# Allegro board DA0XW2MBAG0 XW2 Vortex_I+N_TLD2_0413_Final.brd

Outline 370.48 x 162 mm; copper layers: TOP, GND, IN1, VCC, IN2, IN3, GND1, IN4, GND2, BOTTOM. Coordinates in mm from the lower left corner of the outline.

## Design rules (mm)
net group DFP-S7W4.5(3: nets VGA_XTALIN VGA_XTALOUT
net group W4.5(3)-T1B: nets CLKIN_XTAL_LCP CLKIN_XTAL_LCP_R
net group W4.5(3: nets EC_RST# LPC_ESPI_RESET#_R_R
net group DFP-S3.75(4: nets C_PEG_TXN0 C_PEG_TXN1 C_PEG_TXN2 C_PEG_TXN3 C_PEG_TXN4 C_PEG_TXN5 C_PEG_TXN6 C_PEG_TXN7 C_PEG_TXN8 C_PEG_TXN9 C_PEG_TXN10 C_PEG_TXN11 C_PEG_TXN12 C_PEG_TXN13 C_PEG_TXN14 C_PEG_TXN15 C_PEG_TXP0 C_PEG_TXP1 C_PEG_TXP2 C_PEG_TXP3 C_PEG_TXP4 C_PEG_TXP5 C_PEG_TXP6 C_PEG_TXP7 C_PEG_TXP8 C_PEG_TXP9 C_PEG_TXP10 C_PEG_TXP11 C_PEG_TXP12 C_PEG_TXP13 C_PEG_TXP14 C_PEG_TXP15 PEG_RXN0 PEG_RXN0_C PEG_RXN1 PEG_RXN1_C PEG_RXN2 PEG_RXN2_C PEG_RXN3 PEG_RXN3_C PEG_RXN4 PEG_RXN4_C PEG_RXN5 PEG_RXN5_C PEG_RXN6 PEG_RXN6_C PEG_RXN7 PEG_RXN7_C PEG_RXN8 PEG_RXN8_C PEG_RXN9 PEG_RXN9_C PEG_RXN10 PEG_RXN10_C PEG_RXN11 PEG_RXN11_C PEG_RXN12 PEG_RXN12_C PEG_RXN13 PEG_RXN13_C PEG_RXN14 PEG_RXN14_C PEG_RXN15 PEG_RXN15_C PEG_RXP0 PEG_RXP0_C PEG_RXP1 PEG_RXP1_C PEG_RXP2 PEG_RXP2_C PEG_RXP3 PEG_RXP3_C PEG_RXP4 PEG_RXP4_C PEG_RXP5 PEG_RXP5_C PEG_RXP6 PEG_RXP6_C PEG_RXP7 PEG_RXP7_C PEG_RXP8 PEG_RXP8_C PEG_RXP9 PEG_RXP9_C PEG_RXP10 PEG_RXP10_C PEG_RXP11 PEG_RXP11_C PEG_RXP12 PEG_RXP12_C PEG_RXP13 PEG_RXP13_C PEG_RXP14 PEG_RXP14_C PEG_RXP15 PEG_RXP15_C PEG_TXN0 PEG_TXN1 PEG_TXN2 PEG_TXN3 PEG_TXN4 PEG_TXN5 PEG_TXN6 PEG_TXN7 PEG_TXN8 PEG_TXN9 PEG_TXN10 PEG_TXN11 PEG_TXN12 PEG_TXN13 PEG_TXN14 PEG_TXN15 PEG_TXP0 PEG_TXP1 PEG_TXP2 PEG_TXP3 PEG_TXP4 PEG_TXP5 PEG_TXP6 PEG_TXP7 PEG_TXP8 PEG_TXP9 PEG_TXP10 PEG_TXP11 PEG_TXP12 PEG_TXP13 PEG_TXP14 PEG_TXP15
net group DFP-S4(3.5)W4(3)-T1B: nets DMI_RXN0 DMI_RXN1 DMI_RXN2 DMI_RXN3 DMI_RXP0 DMI_RXP1 DMI_RXP2 DMI_RXP3 DMI_TXN0 DMI_TXN1 DMI_TXN2 DMI_TXN3 DMI_TXP0 DMI_TXP1 DMI_TXP2 DMI_TXP3
net group DFP-S4(3.5)W4(3)-T14B: nets TBTA_DPSRC_AUX_N TBTA_DPSRC_AUX_P TBTB_DPSRC_AUX_N TBTB_DPSRC_AUX_P
net group DFP-S4(3.5)W4.5(3.2)-T3B: nets VMA_CLK0 VMA_CLK0# VMA_CLK1 VMA_CLK1# VMB_CLK0 VMB_CLK0# VMB_CLK1 VMB_CLK1#
net group DFP-S4(3.5: nets CLK_CPU_BCLKN CLK_CPU_BCLKP CLK_DPLL_NSCCLKN CLK_DPLL_NSCCLKP CLK_PCIE_SSD1N CLK_PCIE_SSD1P CLK_PCIE_SSD2N CLK_PCIE_SSD2P CLK_PCIE_TBTN CLK_PCIE_TBTP CLK_PCIE_WLANN CLK_PCIE_WLANP CLK_PCIE_WWANN CLK_PCIE_WWANP CPU_PCI_BCLKN CPU_PCI_BCLKP DDI3_TXN0 DDI3_TXN1 DDI3_TXN2 DDI3_TXN3 DDI3_TXP0 DDI3_TXP1 DDI3_TXP2 DDI3_TXP3 LAN_MX0+ LAN_MX0- LAN_MX1+ LAN_MX1- LAN_MX2+ LAN_MX2- LAN_MX3+ LAN_MX3- MDI0+ MDI0- MDI1+ MDI1- MDI2+ MDI2- MDI3+ MDI3- PCIE_RXN4_WWAN PCIE_RXN5_TBT PCIE_RXN5_TBT_C PCIE_RXN6_TBT PCIE_RXN6_TBT_C PCIE_RXN7_TBT PCIE_RXN7_TBT_C PCIE_RXN8_TBT PCIE_RXN8_TBT_C PCIE_RXN13_LAN PCIE_RXN13_LAN_C PCIE_RXN14_WLAN_C PCIE_RXN17_SSD PCIE_RXN18_SSD PCIE_RXN19_SSD PCIE_RXN20_SSD PCIE_RXP4_WWAN PCIE_RXP5_TBT PCIE_RXP5_TBT_C PCIE_RXP6_TBT PCIE_RXP6_TBT_C PCIE_RXP7_TBT PCIE_RXP7_TBT_C PCIE_RXP8_TBT PCIE_RXP8_TBT_C PCIE_RXP13_LAN PCIE_RXP13_LAN_C PCIE_RXP14_WLAN_C PCIE_RXP17_SSD PCIE_RXP18_SSD PCIE_RXP19_SSD PCIE_RXP20_SSD PCIE_TXN3_CARD PCIE_TXN3_CARD_C PCIE_TXN4_WWAN PCIE_TXN4_WWAN_C PCIE_TXN5_TBT PCIE_TXN5_TBT_C PCIE_TXN6_TBT PCIE_TXN6_TBT_C PCIE_TXN7_TBT PCIE_TXN7_TBT_C PCIE_TXN8_TBT PCIE_TXN8_TBT_C PCIE_TXN13_LAN PCIE_TXN13_LAN_C PCIE_TXN14_WLAN PCIE_TXN14_WLAN_C PCIE_TXN17_SSD PCIE_TXN17_SSD_C PCIE_TXN18_SSD PCIE_TXN18_SSD_C PCIE_TXN19_SSD PCIE_TXN19_SSD_C PCIE_TXN20_SSD PCIE_TXN20_SSD_C PCIE_TXP3_CARD PCIE_TXP3_CARD_C PCIE_TXP4_WWAN PCIE_TXP4_WWAN_C PCIE_TXP5_TBT PCIE_TXP5_TBT_C PCIE_TXP6_TBT PCIE_TXP6_TBT_C PCIE_TXP7_TBT PCIE_TXP7_TBT_C PCIE_TXP8_TBT PCIE_TXP8_TBT_C PCIE_TXP13_LAN PCIE_TXP13_LAN_C PCIE_TXP14_WLAN PCIE_TXP14_WLAN_C PCIE_TXP17_SSD PCIE_TXP17_SSD_C PCIE_TXP18_SSD PCIE_TXP18_SSD_C PCIE_TXP19_SSD PCIE_TXP19_SSD_C PCIE_TXP20_SSD PCIE_TXP20_SSD_C USB30_RX1+ USB30_RX1- USB30_RX3+_C USB30_RX4+_C USB30_RXN3-_C USB30_RXN3-_R USB30_RXN4-_C USB30_RXN4-_R USB30_RXP3+_C USB30_RXP3+_R USB30_RXP4+_C USB30_RXP4+_R USB30_TX1+ USB30_TX1- USB30_TX3+_C_R USB30_TX4+_C_R USB30_TXN1-_C USB30_TXN3-_C USB30_TXN3-_R USB30_TXN4-_C USB30_TXN4-_R USB30_TXP1+_C USB30_TXP3+_C USB30_TXP3+_R USB30_TXP4+_C USB30_TXP4+_R
net group DFP-S4(3.5: nets VMA_WCK01 VMA_WCK01# VMA_WCK23 VMA_WCK23# VMA_WCK45 VMA_WCK45# VMA_WCK67 VMA_WCK67# VMB_WCK01 VMB_WCK01# VMB_WCK23 VMB_WCK23# VMB_WCK45 VMB_WCK45# VMB_WCK67 VMB_WCK67#
net group DFP-S4(3.5: nets DDI1_AUX_SRCN DDI1_AUX_SRCP DDI1_AUXN DDI1_AUXP DDI1_TXN0 DDI1_TXN0_C DDI1_TXN1 DDI1_TXN1_C DDI1_TXN2 DDI1_TXN2_C DDI1_TXN3 DDI1_TXN3_C DDI1_TXP0 DDI1_TXP0_C DDI1_TXP1 DDI1_TXP1_C DDI1_TXP2 DDI1_TXP2_C DDI1_TXP3 DDI1_TXP3_C DDI2_AUX_SRCN DDI2_AUX_SRCP DDI2_AUXN DDI2_AUXP DDI2_TXN0 DDI2_TXN0_C DDI2_TXN1 DDI2_TXN1_C DDI2_TXN2 DDI2_TXN2_C DDI2_TXN3 DDI2_TXN3_C DDI2_TXP0 DDI2_TXP0_C DDI2_TXP1 DDI2_TXP1_C DDI2_TXP2 DDI2_TXP2_C DDI2_TXP3 DDI2_TXP3_C SATA_RXN3 SATA_RXN3_HDD SATA_RXN3_R2 SATA_RXP3 SATA_RXP3_HDD SATA_RXP3_R2 SATA_TXN3 SATA_TXN3_HDD SATA_TXN3_R2 SATA_TXP3 SATA_TXP3_HDD SATA_TXP3_R2 USBP1+ USBP1+_C USBP1- USBP1-_C USBP2+_C USBP2-_C USBP4+ USBP4+_C USBP4+_CHA USBP4- USBP4-_C USBP4-_CHA USBP5+ USBP5+_C USBP5- USBP5-_C USBP7+ USBP7+_C USBP7- USBP7-_C USBP8+_C USBP8-_C USBP9+_R USBP9-_R USBP13+ USBP13-
net group DFP-S4(3.5: nets CK_XDP_N CK_XDP_P CLK_PCIE_GFXN CLK_PCIE_GFXP CLK_PCIE_LANN CLK_PCIE_LANP CLK_PCIE_SDN CLK_PCIE_SDP INT_EDP_AUXN INT_EDP_AUXN_C INT_EDP_AUXP INT_EDP_AUXP_C INT_EDP_TXN0 INT_EDP_TXN0_C INT_EDP_TXN1 INT_EDP_TXN1_C INT_EDP_TXN2 INT_EDP_TXN2_C INT_EDP_TXN3 INT_EDP_TXN3_C INT_EDP_TXP0 INT_EDP_TXP0_C INT_EDP_TXP1 INT_EDP_TXP1_C INT_EDP_TXP2 INT_EDP_TXP2_C INT_EDP_TXP3 INT_EDP_TXP3_C PCIE_RXN3_CARD PCIE_RXN9_SSD PCIE_RXN10_SSD PCIE_RXN11_SSD PCIE_RXN12_SSD PCIE_RXN14_WLAN PCIE_RXP3_CARD PCIE_RXP9_SSD PCIE_RXP10_SSD PCIE_RXP11_SSD PCIE_RXP12_SSD PCIE_RXP14_WLAN PCIE_TXN9_SSD PCIE_TXN9_SSD_C PCIE_TXN10_SSD PCIE_TXN10_SSD_C PCIE_TXN11_SSD PCIE_TXN11_SSD_C PCIE_TXN12_SSD PCIE_TXN12_SSD_C PCIE_TXP9_SSD PCIE_TXP9_SSD_C PCIE_TXP10_SSD PCIE_TXP10_SSD_C PCIE_TXP11_SSD PCIE_TXP11_SSD_C PCIE_TXP12_SSD PCIE_TXP12_SSD_C SATA_RXN3_R1 SATA_RXP3_R1 SATA_TXN3_R1 SATA_TXP3_R1 USB30_RX3+ USB30_RX3- USB30_RX3-_C USB30_RX4+ USB30_RX4- USB30_RX4-_C USB30_TX3+ USB30_TX3- USB30_TX3-_C_R USB30_TX4+ USB30_TX4- USB30_TX4-_C_R USBP2+ USBP2- USBP8+ USBP8- USBP9+ USBP9- USBP11+ USBP11+_BOT USBP11+_TOP USBP11- USBP11-_BOT USBP11-_TOP USBP13+_BOT USBP13+_TOP USBP13-_BOT USBP13-_TOP USBP14+ USBP14-
net group DFP-S4(4: nets CNV_WR_CLKN CNV_WR_CLKP CNV_WRXN0 CNV_WRXN1 CNV_WRXP0 CNV_WRXP1 CNV_WT_CLKN CNV_WT_CLKP CNV_WTXN0 CNV_WTXN1 CNV_WTXP0 CNV_WTXP1
net group DFP-S4W4-TB: nets TBTA_AUX_N TBTA_AUX_P TBTA_CA2HD_1_RX_N TBTA_CA2HD_1_RX_P TBTA_CA2HD_2_RX_N TBTA_CA2HD_2_RX_P TBTA_HD2CA_1_TX_N TBTA_HD2CA_1_TX_P TBTA_HD2CA_2_TX_N TBTA_HD2CA_2_TX_P TBTA_RX1_N TBTA_RX1_P TBTA_RX1N_R TBTA_RX1P_R TBTA_RX2_N TBTA_RX2_P TBTA_RX2N_R TBTA_RX2P_R TBTA_TX1_N TBTA_TX1_P TBTA_TX1N_R TBTA_TX1P_R TBTA_TX2_N TBTA_TX2_P TBTA_TX2N_R TBTA_TX2P_R TBTB_AUX_N TBTB_AUX_P TBTB_CA2HD_1_RX_N TBTB_CA2HD_1_RX_P TBTB_CA2HD_2_RX_N TBTB_CA2HD_2_RX_P TBTB_HD2CA_1_TX_N TBTB_HD2CA_1_TX_P TBTB_HD2CA_2_TX_N TBTB_HD2CA_2_TX_P TBTB_RX1_N TBTB_RX1_P TBTB_RX1N_R TBTB_RX1P_R TBTB_RX2_N TBTB_RX2_P TBTB_RX2N_R TBTB_RX2P_R TBTB_TX1_N TBTB_TX1_P TBTB_TX1N_R TBTB_TX1P_R TBTB_TX2_N TBTB_TX2_P TBTB_TX2N_R TBTB_TX2P_R
net group DFP-S6(4.5)W4.5(3)-T1B: nets M_B_CLKN0 M_B_CLKN1 M_B_CLKN2 M_B_CLKN3 M_B_CLKP0 M_B_CLKP1 M_B_CLKP2 M_B_CLKP3
net group DFP-S6(4.5)W4.5(3)-T4B: nets M_A_CLKN0 M_A_CLKN1 M_A_CLKN2 M_A_CLKN3 M_A_CLKP0 M_A_CLKP1 M_A_CLKP2 M_A_CLKP3
net group DFP-S7(5: nets EXT_DPE_AUXN EXT_DPE_AUXP EXT_DPE_TXN0 EXT_DPE_TXN0_C EXT_DPE_TXN1 EXT_DPE_TXN1_C EXT_DPE_TXN2 EXT_DPE_TXN2_C EXT_DPE_TXN3 EXT_DPE_TXN3_C EXT_DPE_TXP0 EXT_DPE_TXP0_C EXT_DPE_TXP1 EXT_DPE_TXP1_C EXT_DPE_TXP2 EXT_DPE_TXP2_C EXT_DPE_TXP3 EXT_DPE_TXP3_C EXT_DPF_AUXN EXT_DPF_AUXP EXT_DPF_TXN0 EXT_DPF_TXN0_C EXT_DPF_TXN1 EXT_DPF_TXN1_C EXT_DPF_TXN2 EXT_DPF_TXN2_C EXT_DPF_TXN3 EXT_DPF_TXN3_C EXT_DPF_TXP0 EXT_DPF_TXP0_C EXT_DPF_TXP1 EXT_DPF_TXP1_C EXT_DPF_TXP2 EXT_DPF_TXP2_C EXT_DPF_TXP3 EXT_DPF_TXP3_C
net group DFP-S7(5: nets EDP_AUXN_OUT EDP_AUXN_OUT_R EDP_AUXP_OUT EDP_AUXP_OUT_R EDP_TXN0_OUT EDP_TXN0_OUT_R EDP_TXN1_OUT EDP_TXN1_OUT_R EDP_TXN2_OUT EDP_TXN2_OUT_R EDP_TXN3_OUT EDP_TXN3_OUT_R EDP_TXP0_OUT EDP_TXP0_OUT_R EDP_TXP1_OUT EDP_TXP1_OUT_R EDP_TXP2_OUT EDP_TXP2_OUT_R EDP_TXP3_OUT EDP_TXP3_OUT_R EXT_EDP_AUXN EXT_EDP_AUXN_C EXT_EDP_AUXP EXT_EDP_AUXP_C EXT_EDP_TXN0 EXT_EDP_TXN0_C EXT_EDP_TXN1 EXT_EDP_TXN1_C EXT_EDP_TXN2 EXT_EDP_TXN2_C EXT_EDP_TXN3 EXT_EDP_TXN3_C EXT_EDP_TXP0 EXT_EDP_TXP0_C EXT_EDP_TXP1 EXT_EDP_TXP1_C EXT_EDP_TXP2 EXT_EDP_TXP2_C EXT_EDP_TXP3 EXT_EDP_TXP3_C
net group DFP-S7W4.5-TB: nets EXT_DPE_AUX_SRCN EXT_DPE_AUX_SRCP EXT_DPF_AUX_SRCN EXT_DPF_AUX_SRCP
net group DFP-S9(5)W7(4.5)-T1B: nets M_B_DQSN0 M_B_DQSN1 M_B_DQSN2 M_B_DQSN3 M_B_DQSN4 M_B_DQSN5 M_B_DQSN6 M_B_DQSN7 M_B_DQSN8 M_B_DQSP0 M_B_DQSP1 M_B_DQSP2 M_B_DQSP3 M_B_DQSP4 M_B_DQSP5 M_B_DQSP6 M_B_DQSP7 M_B_DQSP8
net group DFP-S9(5)W7(4.5)-T4B: nets M_A_DQSN0 M_A_DQSN1 M_A_DQSN2 M_A_DQSN3 M_A_DQSN4 M_A_DQSN5 M_A_DQSN6 M_A_DQSN7 M_A_DQSN8 M_A_DQSP0 M_A_DQSP1 M_A_DQSP2 M_A_DQSP3 M_A_DQSP4 M_A_DQSP5 M_A_DQSP6 M_A_DQSP7 M_A_DQSP8
net group DFP-S9(7: nets C_IN_CLK#_R C_IN_CLK#_R_R C_IN_CLK_R C_IN_CLK_R_R C_TX0_HDMI+_R C_TX0_HDMI+_R_R C_TX0_HDMI-_R C_TX0_HDMI-_R_R C_TX1_HDMI+_R C_TX1_HDMI+_R_R C_TX1_HDMI-_R C_TX1_HDMI-_R_R C_TX2_HDMI+_R C_TX2_HDMI+_R_R C_TX2_HDMI-_R C_TX2_HDMI-_R_R
net group DFP-S9(15: nets DPSNK0_AUX_N DPSNK0_AUX_P DPSNK0_ML0_N DPSNK0_ML0_P DPSNK0_ML1_N DPSNK0_ML1_P DPSNK0_ML2_N DPSNK0_ML2_P DPSNK0_ML3_N DPSNK0_ML3_P DPSNK1_AUX_N DPSNK1_AUX_P DPSNK1_ML0_N DPSNK1_ML0_P DPSNK1_ML1_N DPSNK1_ML1_P DPSNK1_ML2_N DPSNK1_ML2_P DPSNK1_ML3_N DPSNK1_ML3_P TBT_SNK0_AUX_N TBT_SNK0_AUX_P TBT_SNK0_AUXN_R TBT_SNK0_AUXP_R TBT_SNK0_ML0_N TBT_SNK0_ML0_N_L TBT_SNK0_ML0_P TBT_SNK0_ML0_P_L TBT_SNK0_ML1_N TBT_SNK0_ML1_N_L TBT_SNK0_ML1_P TBT_SNK0_ML1_P_L TBT_SNK0_ML2_N TBT_SNK0_ML2_N_L TBT_SNK0_ML2_P TBT_SNK0_ML2_P_L TBT_SNK0_ML3_N TBT_SNK0_ML3_N_L TBT_SNK0_ML3_P TBT_SNK0_ML3_P_L TBT_SNK1_AUX_N TBT_SNK1_AUX_P TBT_SNK1_AUXN_R TBT_SNK1_AUXP_R TBT_SNK1_ML0_N TBT_SNK1_ML0_N_L TBT_SNK1_ML0_P TBT_SNK1_ML0_P_L TBT_SNK1_ML1_N TBT_SNK1_ML1_N_L TBT_SNK1_ML1_P TBT_SNK1_ML1_P_L TBT_SNK1_ML2_N TBT_SNK1_ML2_N_L TBT_SNK1_ML2_P TBT_SNK1_ML2_P_L TBT_SNK1_ML3_N TBT_SNK1_ML3_N_L TBT_SNK1_ML3_P TBT_SNK1_ML3_P_L
net group DFP-S9(15: nets EXT_DPC_TXN0 EXT_DPC_TXN1 EXT_DPC_TXN2 EXT_DPC_TXN3 EXT_DPC_TXP0 EXT_DPC_TXP1 EXT_DPC_TXP2 EXT_DPC_TXP3
net group W4-T14B: nets USB2_COMP
net group W4.5(3)-T14B: nets ESPI_CS#_L ESPI_EC_IO0 ESPI_EC_IO0_R ESPI_EC_IO1 ESPI_EC_IO1_R ESPI_EC_IO2 ESPI_EC_IO2_R ESPI_EC_IO3 ESPI_EC_IO3_R LPC_ESPI_CLK_R_R LPC_ESPI_RESET#_R PCH_SPI1_SO_L PCH_SPI_CS0#_L PCH_SPI_IO2_ROM PCH_SPI_IO3_ROM PVT_CS# PVT_MOSI PVT_MOSI_L PVT_SCLK PVT_SCLK_L PVT_SPI_MISO PVT_SPI_MISO_R SPI1_CLK_EC SPI1_CLK_ROM SPI1_IO2 SPI1_IO3 SPI1_SI_EC SPI1_SI_ROM SPI1_SO_EC SPI1_SO_ROM SPI_CS0#_EC SPI_TPM_CS# SPI_TPM_CS#_L SPI_TPM_CS#_R
net group W4.5(3: nets EXT_DPC_SCL EXT_DPC_SDA HDMI_SCL_R_R HDMI_SDA_R_R IFPC_SCL IFPC_SDA LAN_XTAL1 LAN_XTAL2 RTC_X1 RTC_X2 TBT_XTAL_25_IN TBT_XTAL_25_OUT XTAL24_IN XTAL24_IN_L XTAL24_OUT XTAL24_OUT_L XTAL_25_IN XTAL_25_OUT XTALOUTBUFF XTALSSIN
net group W4.5(3: nets ACE_I2C_SCL2 ACE_I2C_SDA2 ACZ_BCLK ACZ_SDO ACZ_SDOUT_AUDIO ACZ_SYNC ACZ_SYNC_AUDIO AMP_DATA_A AMP_DATA_B AMP_DATAO_BOT_LEFT AMP_DATAO_TOP_RIGHT AUD_AZACPU_SCLK AUD_AZACPU_SCLK_R AUD_AZACPU_SDI AUD_AZACPU_SDI_R AUD_AZACPU_SDO AUD_AZACPU_SDO_R BIT_CLK_AUDIO BIT_CLK_AUDIO_R BQSCL BQSDA DIGITAL_CLK1 DIGITAL_CLK2 DIGITAL_D1 DIGITAL_D2 DMIC_3_CLK1_R DMIC_3_CLK2_R DMIC_3_D1_R DMIC_3_D2_L DMIC_3_D2_R DMIC_CLK1_R DMIC_CLK2_R GFX_SCL GFX_SDA HDMI_SCL_R HDMI_SDA_R HDMI_UP_CLK HDMI_UP_DATA I2C_C1_CLK I2C_C1_DATA I2C_NXP_SCL_L_AUDIO I2C_SCL_AMP I2C_SDA_AMP I2C_TS_SCL I2C_TS_SDA MP2949A_ALT# MP2949A_SCL_P MP2949A_SCLK MP2949A_SDA_P MP2949A_SDIO NFC_SML0_CLK NFC_SML0_DATA PCH_KBC_CLK PCH_KBC_DATA PCH_KBC_SMCLK PCH_KBC_SMDATA PCH_SMBCLK PCH_SMBDATA PCH_SPI1_CLK_L PCH_SPI1_SI_L PD_I2C_SCL3 PD_I2C_SDA3 SCL_BAT_CHG SDA_BAT_CHG SMBCLK SMBDATA SPI1_CLK SPI1_SI SPI1_SO SPI_CS0# SUS_CLK_WLAN SUSCLK32 SUSCLK32_KBC TBT_EE_CLK TBT_EE_CS_N TBT_EE_DI TBT_EE_DO TBT_I2C_SCL TBT_I2C_SDA THERM_SCL THERM_SDA VR_SCL_P VR_SDA_P VR_SVID_ALERT# VR_SVID_CLK VR_SVID_DATA WIFI_32KHZ
net group W4.5(3: nets ACZ_RST# ACZ_RST#_AUDIO ACZ_SDIN0 ACZ_SDIN0_R AUDIOAMPS_CLK AUDIOAMPS_DAT DDR_PG_CNTL DDR_VTT_PG_CTRL ESPI_CLK_EC ESPI_CLK_EC_R ESPI_CS# ESPI_EC_IO0_L ESPI_EC_IO1_L ESPI_EC_IO2_L ESPI_EC_IO3_L EXP_CLK_REQ7# FAN1_PWM FAN1_PWM_Y FAN2_PWM FAN2_PWM_Y GPU_CLK_REQ1# HD_SDIN0 I2C_CLICK_SCL I2C_CLICK_SDA I2C_NXP_SCL_L I2C_NXP_SDA_L I2S1_BCLK I2S1_CODEC_RX_DAT I2S1_CODEC_TX_CLK I2S1_CODEC_TX_DAT I2S1_CODEC_TX_WS I2S1_MCLK I2S1_RX_DAT I2S1_TX_CLK I2S1_TX_DAT I2S1_TX_WS PCIE_CLKREQ9# SSD1_CLK_REQ0# SSD2_CLK_REQ6# TACH_FAN1_IN TACH_FAN2_IN TBT_CLK_REQ5# UIM_CLK UIM_DATA UIM_RESET WLAN_CLK_REQ3# WWAN_CLK_REQ8#
net group W5-T1234B: nets 1V05A_PG 1V8A_PG 2V5_PG 3V3DS_PG CPU_PLTRST#R DPWROK EN_1V05A EN_2V5 EN_P1V5S EN_PVCCIO EN_VRPVDDQ EN_VRPVTT KBC_PWR_ON PCH_PECI PCH_PWROK PCH_SLP_S0IX# PCI_PLTRST# PECI PLT_RST# PM_PWROK PM_THRMTRIP# PM_THRMTRIP#_L PVCORE_PG PWR_GOOD_3 RSMRST# RSMRST_PG RTC_RST# SLP_A# SLP_LAN# SLP_S3# SLP_S4# SLP_S5# SRTC_RST# VCCIO_PG VRAVR_ON VRPVDDQ_PG
net group W5.5(3.5: nets FBA_DBI0 FBA_DBI1 FBA_DBI2 FBA_DBI3 FBA_DBI4 FBA_DBI5 FBA_DBI6 FBA_DBI7 FBA_EDC0 FBA_EDC1 FBA_EDC2 FBA_EDC3 FBA_EDC4 FBA_EDC5 FBA_EDC6 FBA_EDC7 FBB_DBI0 FBB_DBI1 FBB_DBI2 FBB_DBI3 FBB_DBI4 FBB_DBI5 FBB_DBI6 FBB_DBI7 FBB_EDC0 FBB_EDC1 FBB_EDC2 FBB_EDC3 FBB_EDC4 FBB_EDC5 FBB_EDC6 FBB_EDC7 VMA_DQ0 VMA_DQ1 VMA_DQ2 VMA_DQ3 VMA_DQ4 VMA_DQ5 VMA_DQ6 VMA_DQ7 VMA_DQ8 VMA_DQ9 VMA_DQ10 VMA_DQ11 VMA_DQ12 VMA_DQ13 VMA_DQ14 VMA_DQ15 VMA_DQ16 VMA_DQ17 VMA_DQ18 VMA_DQ19 VMA_DQ20 VMA_DQ21 VMA_DQ22 VMA_DQ23 VMA_DQ24 VMA_DQ25 VMA_DQ26 VMA_DQ27 VMA_DQ28 VMA_DQ29 VMA_DQ30 VMA_DQ31 VMA_DQ32 VMA_DQ33 VMA_DQ34 VMA_DQ35 VMA_DQ36 VMA_DQ37 VMA_DQ38 VMA_DQ39 VMA_DQ40 VMA_DQ41 VMA_DQ42 VMA_DQ43 VMA_DQ44 VMA_DQ45 VMA_DQ46 VMA_DQ47 VMA_DQ48 VMA_DQ49 VMA_DQ50 VMA_DQ51 VMA_DQ52 VMA_DQ53 VMA_DQ54 VMA_DQ55 VMA_DQ56 VMA_DQ57 VMA_DQ58 VMA_DQ59 VMA_DQ60 VMA_DQ61 VMA_DQ62 VMA_DQ63 VMB_DQ0 VMB_DQ1 VMB_DQ2 VMB_DQ3 VMB_DQ4 VMB_DQ5 VMB_DQ6 VMB_DQ7 VMB_DQ8 VMB_DQ9 VMB_DQ10 VMB_DQ11 VMB_DQ12 VMB_DQ13 VMB_DQ14 VMB_DQ15 VMB_DQ16 VMB_DQ17 VMB_DQ18 VMB_DQ19 VMB_DQ20 VMB_DQ21 VMB_DQ22 VMB_DQ23 VMB_DQ24 VMB_DQ25 VMB_DQ26 VMB_DQ27 VMB_DQ28 VMB_DQ29 VMB_DQ30 VMB_DQ31 VMB_DQ32 VMB_DQ33 VMB_DQ34 VMB_DQ35 VMB_DQ36 VMB_DQ37 VMB_DQ38 VMB_DQ39 VMB_DQ40 VMB_DQ41 VMB_DQ42 VMB_DQ43 VMB_DQ44 VMB_DQ45 VMB_DQ46 VMB_DQ47 VMB_DQ48 VMB_DQ49 VMB_DQ50 VMB_DQ51 VMB_DQ52 VMB_DQ53 VMB_DQ54 VMB_DQ55 VMB_DQ56 VMB_DQ57 VMB_DQ58 VMB_DQ59 VMB_DQ60 VMB_DQ61 VMB_DQ62 VMB_DQ63
net group W5.5(3.5: nets FBA_CMD0 FBA_CMD1 FBA_CMD2 FBA_CMD3 FBA_CMD4 FBA_CMD5 FBA_CMD6 FBA_CMD7 FBA_CMD8 FBA_CMD9 FBA_CMD10 FBA_CMD11 FBA_CMD12 FBA_CMD13 FBA_CMD14 FBA_CMD15 FBA_CMD16 FBA_CMD17 FBA_CMD18 FBA_CMD19 FBA_CMD20 FBA_CMD21 FBA_CMD22 FBA_CMD23 FBA_CMD24 FBA_CMD25 FBA_CMD26 FBA_CMD27 FBA_CMD28 FBA_CMD29 FBA_CMD30 FBA_CMD31 FBB_CMD0 FBB_CMD1 FBB_CMD2 FBB_CMD3 FBB_CMD4 FBB_CMD5 FBB_CMD6 FBB_CMD7 FBB_CMD8 FBB_CMD9 FBB_CMD10 FBB_CMD11 FBB_CMD12 FBB_CMD13 FBB_CMD14 FBB_CMD15 FBB_CMD16 FBB_CMD17 FBB_CMD18 FBB_CMD19 FBB_CMD20 FBB_CMD21 FBB_CMD22 FBB_CMD23 FBB_CMD24 FBB_CMD25 FBB_CMD26 FBB_CMD27 FBB_CMD28 FBB_CMD29 FBB_CMD30 FBB_CMD31
net group W6.5(4)-T1B: nets M_B_CB0 M_B_CB1 M_B_CB2 M_B_CB3 M_B_CB4 M_B_CB5 M_B_CB6 M_B_CB7 M_B_DQ0 M_B_DQ1 M_B_DQ2 M_B_DQ3 M_B_DQ4 M_B_DQ5 M_B_DQ6 M_B_DQ7 M_B_DQ8 M_B_DQ9 M_B_DQ10 M_B_DQ11 M_B_DQ12 M_B_DQ13 M_B_DQ14 M_B_DQ15 M_B_DQ16 M_B_DQ17 M_B_DQ18 M_B_DQ19 M_B_DQ20 M_B_DQ21 M_B_DQ22 M_B_DQ23 M_B_DQ24 M_B_DQ25 M_B_DQ26 M_B_DQ27 M_B_DQ28 M_B_DQ29 M_B_DQ30 M_B_DQ31 M_B_DQ32 M_B_DQ33 M_B_DQ34 M_B_DQ35 M_B_DQ36 M_B_DQ37 M_B_DQ38 M_B_DQ39 M_B_DQ40 M_B_DQ41 M_B_DQ42 M_B_DQ43 M_B_DQ44 M_B_DQ45 M_B_DQ46 M_B_DQ47 M_B_DQ48 M_B_DQ49 M_B_DQ50 M_B_DQ51 M_B_DQ52 M_B_DQ53 M_B_DQ54 M_B_DQ55 M_B_DQ56 M_B_DQ57 M_B_DQ58 M_B_DQ59 M_B_DQ60 M_B_DQ61 M_B_DQ62 M_B_DQ63
net group W6.5(4)-T4B: nets M_A_CB0 M_A_CB1 M_A_CB2 M_A_CB3 M_A_CB4 M_A_CB5 M_A_CB6 M_A_CB7 M_A_DQ0 M_A_DQ1 M_A_DQ2 M_A_DQ3 M_A_DQ4 M_A_DQ5 M_A_DQ6 M_A_DQ7 M_A_DQ8 M_A_DQ9 M_A_DQ10 M_A_DQ11 M_A_DQ12 M_A_DQ13 M_A_DQ14 M_A_DQ15 M_A_DQ16 M_A_DQ17 M_A_DQ18 M_A_DQ19 M_A_DQ20 M_A_DQ21 M_A_DQ22 M_A_DQ23 M_A_DQ24 M_A_DQ25 M_A_DQ26 M_A_DQ27 M_A_DQ28 M_A_DQ29 M_A_DQ30 M_A_DQ31 M_A_DQ32 M_A_DQ33 M_A_DQ34 M_A_DQ35 M_A_DQ36 M_A_DQ37 M_A_DQ38 M_A_DQ39 M_A_DQ40 M_A_DQ41 M_A_DQ42 M_A_DQ43 M_A_DQ44 M_A_DQ45 M_A_DQ46 M_A_DQ47 M_A_DQ48 M_A_DQ49 M_A_DQ50 M_A_DQ51 M_A_DQ52 M_A_DQ53 M_A_DQ54 M_A_DQ55 M_A_DQ56 M_A_DQ57 M_A_DQ58 M_A_DQ59 M_A_DQ60 M_A_DQ61 M_A_DQ62 M_A_DQ63
net group W7(4.5)-T1B: nets DDR1_PAR DDRB_ACT# M_B_BG#0 M_B_BG#1 M_B_BS#0 M_B_BS#1 M_B_CKE0 M_B_CKE1 M_B_CKE2 M_B_CKE3 M_B_CS#0 M_B_CS#1 M_B_CS#2 M_B_CS#3 M_B_ODT0 M_B_ODT1 M_B_ODT2 M_B_ODT3
net group W7(4.5)-T4B: nets DDR0_PAR DDRA_ACT# M_A_BG#0 M_A_BG#1 M_A_BS#0 M_A_BS#1 M_A_CKE0 M_A_CKE1 M_A_CKE2 M_A_CKE3 M_A_CS#0 M_A_CS#1 M_A_CS#2 M_A_CS#3 M_A_ODT0 M_A_ODT1 M_A_ODT2 M_A_ODT3
net group W8.5(6)-T1B: nets DDR1_ALERT# M_B_A0 M_B_A1 M_B_A2 M_B_A3 M_B_A4 M_B_A5 M_B_A6 M_B_A7 M_B_A8 M_B_A9 M_B_A10 M_B_A11 M_B_A12 M_B_A13 M_B_A14 M_B_A15 M_B_A16
net group W8.5(6)-T4B: nets DDR0_ALERT# M_A_A0 M_A_A1 M_A_A2 M_A_A3 M_A_A4 M_A_A5 M_A_A6 M_A_A7 M_A_A8 M_A_A9 M_A_A10 M_A_A11 M_A_A12 M_A_A13 M_A_A14 M_A_A15 M_A_A16
net group W10-T14B: nets CNV_RCOMP EDP_RCOMP PEG_COMP
net group W10-T134B: nets HPOUT_L HPOUT_R PORTD_A
net group W10-T1234B: nets +1.8V_AMP +1.8V_CPAVDD18 +1.8V_VDD18 +3V_ALW +3V_CAM +3V_FP +3V_RTC +3V_RTC_0 +3V_RTC_1 +3V_RTC_2 +3V_TS +3V_WLAN_P +3V_WWAN_P +3VLCD_CON +5V_HDD +5V_HDMIC +5V_IR_LED +5V_LED_KBLIGHT +G_SEN_PW +PVT_VCC +SPI_VCC +UIM_PWR +VCC3P3_SX +VDD_HDA +VDD_I2S +VDD_IO +VHIF +VIN_BLIGHT +VSPI CP_VNEG CP_VPOS EXT_MIC_L FLY_N FLY_P IO_VDD TPM_VDD1 WIFI_3V
net group W15-T4B: nets SM_RCOMP_0 SM_RCOMP_1 SM_RCOMP_2
net group W15-T1234B: nets CORE_PLLVDD
net group W20-T1234B: nets +5V_AUDIO SMDDR_VREF_CA_A SMDDR_VREF_DQ1_M3
net group W50-T1234B: nets +5V_AMP
net group W60(60)-T134B: nets L_SPK+ L_SPK+_R L_SPK- L_SPK-_R OUT_L_A OUT_L_B OUT_R_A OUT_R_B R_SPK+ R_SPK+_R R_SPK- R_SPK-_R

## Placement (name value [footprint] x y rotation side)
C400  0.1u/16V_4  [C0402]  79.15 60.54 180 bottom
C500  0.22U/10V_4  [C0402]  324.01 49.37 270 bottom
C501  0.1u/16V_4  [C0402]  317.41 58.76 0 bottom
C502  0.1u/16V_4  [C0402]  320.83 66.38 0 bottom
C503  0.1u/16V_4  [C0402]  320.83 63.34 0 bottom
C504  0.1u/16V_4  [C0402]  329.85 61.05 180 bottom
C505  0.1u/16V_4  [C0402]  330.49 51.65 90 bottom
C506  0.1u/16V_4  [C0402]  317.41 61.05 0 bottom
C507  0.1u/16V_4  [C0402]  331.65 60.82 180 bottom
C508  0.1u/16V_4  [C0402]  331.65 59.86 180 bottom
C509  0.1u/16V_4  [C0402]  318.8 53.68 90 bottom
C510  0.1u/16V_4  [C0402]  329.47 51.65 90 bottom
C511  0.1u/16V_4  [C0402]  320.83 65.37 0 bottom
C512  0.1u/16V_4  [C0402]  320.83 64.35 0 bottom
C513  0.1u/16V_4  [C0402]  329.47 62.45 270 bottom
C514  0.22U/10V_4  [C0402]  322.99 49.37 270 bottom
C515  0.22U/10V_4  [C0402]  322.74 51.83 270 bottom
C516  0.22U/10V_4  [C0402]  321.72 51.83 270 bottom
C517  0.22U/10V_4  [C0402]  321.47 49.44 270 bottom
C518  0.22U/10V_4  [C0402]  319.89 51.7 270 bottom
C519  0.22U/10V_4  [C0402]  318.88 51.7 270 bottom
C520  0.22U/10V_4  [C0402]  320.45 49.44 270 bottom
C521  0.1U/16V_4  [C0402]  333.03 55.72 0 bottom
C522  0.1U/16V_4  [C0402]  333.03 56.73 0 bottom
C523  0.22U/10V_4  [C0402]  329.09 49.37 270 bottom
C524  0.22U/10V_4  [C0402]  328.07 49.37 270 bottom
C525  0.22U/10V_4  [C0402]  327.82 51.53 270 bottom
C526  0.22U/10V_4  [C0402]  326.8 51.53 270 bottom
C527  0.22U/10V_4  [C0402]  326.55 49.37 270 bottom
C528  0.22U/10V_4  [C0402]  325.53 49.37 270 bottom
C529  0.22U/10V_4  [C0402]  325.28 51.53 270 bottom
C530  0.22U/10V_4  [C0402]  324.26 51.53 270 bottom
C531  0.1U/16V_4  [C0402]  333.03 53.68 0 bottom
C532  0.1U/16V_4  [C0402]  333.03 54.7 0 bottom
C533  0.1u/16V_4  [C0402]  341.41 47.72 270 bottom
C534  0.1u/16V_4  [C0402]  338.86 33.14 90 bottom
C535  0.1u/16V_4  [C0402]  346.49 30.57 180 bottom
C536  0.1u/16V_4  [C0402]  346.49 31.59 180 bottom
C537  0.1u/16V_4  [C0402]  343.69 47.72 270 bottom
C538  0.1u/16V_4  [C0402]  334.27 33.16 0 bottom
C539  0.1u/16V_4  [C0402]  332.7 46.7 90 bottom
C540  0.1u/16V_4  [C0402]  347 43.14 270 bottom
C541  0.1u/16V_4  [C0402]  349.03 43.14 270 bottom
C542  0.1u/16V_4  [C0402]  348.01 43.14 270 bottom
C543  0.1u/16V_4  [C0402]  346.49 33.75 180 bottom
C544  0.1u/16V_4  [C0402]  346.49 32.73 180 bottom
C545  0.1u/16V_4  [C0402]  345.98 43.14 270 bottom
C546  0.22U/10V_4  [C0402]  330.51 41.87 180 bottom
C547  0.22U/10V_4  [C0402]  334.8 43.02 180 bottom
C548  0.22U/10V_4  [C0402]  334.8 44.03 180 bottom
C549  0.22U/10V_4  [C0402]  332.9 43.88 180 bottom
C550  0.22U/10V_4  [C0402]  332.9 44.85 180 bottom
C551  0.22U/10V_4  [C0402]  334.8 45.3 180 bottom
C552  0.22U/10V_4  [C0402]  334.8 46.32 180 bottom
C553  0.1U/16V_4  [C0402]  340.11 30.82 270 bottom
C554  0.1U/16V_4  [C0402]  341.13 30.82 270 bottom
C555  0.22U/10V_4  [C0402]  330.51 42.89 180 bottom
C556  0.22U/10V_4  [C0402]  333.36 34.13 180 bottom
C557  0.22U/10V_4  [C0402]  333.36 35.14 180 bottom
C558  0.22U/10V_4  [C0402]  334.8 37.17 180 bottom
C559  0.22U/10V_4  [C0402]  334.8 38.19 180 bottom
C560  0.22U/10V_4  [C0402]  331.96 39.33 180 bottom
C561  0.22U/10V_4  [C0402]  331.96 40.35 180 bottom
C562  0.22U/10V_4  [C0402]  334.8 40.6 180 bottom
C563  0.22U/10V_4  [C0402]  334.8 41.62 180 bottom
C564  0.1U/16V_4  [C0402]  337.37 30.65 180 bottom
C565  0.1U/16V_4  [C0402]  337.37 29.66 180 bottom
C585  0.1U/16V_2  [C0201]  352.3 54.45 180 bottom
C586  0.1U/16V_2  [C0201]  352.3 55.59 180 bottom
C587  0.1U/16V_2  [C0201]  352.3 52.16 180 bottom
C588  0.1U/16V_2  [C0201]  352.3 53.3 180 bottom
C589  0.1U/16V_2  [C0201]  352.3 49.87 180 bottom
C590  0.1U/16V_2  [C0201]  352.3 51.02 180 bottom
C591  0.1U/16V_2  [C0201]  352.3 47.59 180 bottom
C592  0.1U/16V_2  [C0201]  352.3 48.73 180 bottom
C593  *0.1U/16V_2  [C0201]  351.31 54.45 0 bottom
C594  *0.1U/16V_2  [C0201]  351.31 55.59 0 bottom
C595  *0.1U/16V_2  [C0201]  351.31 52.16 0 bottom
C596  *0.1U/16V_2  [C0201]  351.31 53.3 0 bottom
C597  *0.1U/16V_2  [C0201]  351.31 49.87 0 bottom
C598  *0.1U/16V_2  [C0201]  351.31 51.02 0 bottom
C599  *0.1U/16V_2  [C0201]  351.31 47.59 0 bottom
C600  *0.1U/16V_2  [C0201]  351.31 48.73 0 bottom
C602  0.1u/16V_4  [C0402]  354.36 70.7 270 top
C605  0.1u/16V_4  [C0402]  19.21 106.14 0 bottom
C607  0.1u/16V_4  [C0402]  19.21 105.12 0 bottom
C608  0.1u/16V_4  [C0402]  20.83 86.63 0 bottom
C609  0.1u/16V_4  [C0402]  20.83 87.64 0 bottom
C610  0.1u/16V_4  [C0402]  353.35 70.7 270 top
C612  0.1u/16V_4  [C0402]  27.39 107.53 0 bottom
C613  0.1u/16V_4  [C0402]  29.8 89.85 0 bottom
C615  0.1u/16V_4  [C0402]  27.39 108.55 0 bottom
C616  0.1u/16V_4  [C0402]  29.8 90.87 0 bottom
C618  0.1u/16V_4  [C0402]  20.48 107.15 0 bottom
C619  0.1u/16V_4  [C0402]  22.26 88.74 0 bottom
C621  0.1u/16V_4  [C0402]  64.17 45.56 270 top
C625  0.01U/50V_4  [C0402]  63.43 54.78 90 top
C627  0.01U/50V_4  [C0402]  63.15 45.56 90 top
C628  0.01U/50V_4  [C0402]  62.41 54.78 90 top
C629  0.01U/50V_4  [C0402]  62.14 45.56 90 top
C630  0.01U/50V_4  [C0402]  61.12 54.78 90 top
C631  0.01U/50V_4  [C0402]  60.28 45.56 90 top
C632  0.01U/50V_4  [C0402]  60.1 54.78 90 top
C633  0.01U/50V_4  [C0402]  59.26 45.56 90 top
C634  0.1u/16V_4  [C0402]  57.28 49.62 0 top
C635  0.1u/16V_4  [C0402]  56.78 52.29 180 top
C652  0.1u/16V_4  [C0402]  58.17 51.07 270 top
C653  0.01U/50V_4  [C0402]  56.78 51.3 180 top
C858  1u/10V_4  [C0402]  254.03 32.96 0 top
C859  1u/10V_4  [C0402]  256.52 33.24 270 top
C1000  0.022U/25V_4  [C0402]  132.54 25.87 0 bottom
C1001  *0.1u/16V_4  [C0402]  142.02 22.82 0 bottom
C1002  1U/6.3V_2  [C0201]  125.18 27.24 270 bottom
C1003  1U/6.3V_2  [C0201]  162.85 27.27 270 bottom
C1004  1U/6.3V_2  [C0201]  134.02 44.41 0 top
C1005  1U/6.3V_2  [C0201]  159.16 27.27 270 bottom
C1006  1U/6.3V_2  [C0201]  152.94 27.4 270 bottom
C1007  1U/6.3V_2  [C0201]  154.31 44.41 0 top
C1008  1U/6.3V_2  [C0201]  172.37 44.41 0 top
C1009  1U/6.3V_2  [C0201]  117.38 44.41 0 top
C1010  10U/6.3V_4  [C0402]  113.82 44.41 0 top
C1011  10U/6.3V_4  [C0402]  120.68 44.41 180 top
C1012  10U/6.3V_4  [C0402]  130.21 44.41 0 top
C1013  10U/6.3V_4  [C0402]  161.07 44.41 0 top
C1014  10U/6.3V_4  [C0402]  141 44.41 0 top
C1015  10U/6.3V_4  [C0402]  135.41 44.41 0 top
C1016  10U/6.3V_4  [C0402]  165.89 44.41 180 top
C1017  10U/6.3V_4  [C0402]  174.15 44.41 0 top
C1018  0.1U/16V_2  [C0201]  156.62 44.41 0 bottom
C1019  1U/6.3V_2  [C0201]  166.66 26.89 270 bottom
C1020  *2.2U/10V_4  [C0402]  135.41 26.38 270 bottom
C1021  1U/6.3V_2  [C0201]  188.75 56.48 180 top
C1022  10U/6.3V_4  [C0402]  169.96 26.89 90 bottom
C1023  *1U/6.3V_2  [C0201]  182.15 44.79 180 top
C1024  0.1U/16V_2  [C0201]  183.85 44.03 180 bottom
C1025  1U/6.3V_2  [C0201]  171.48 21.3 270 bottom
C1026  2.2U/10V_4  [C0402]  178.09 44.41 180 top
C1027  10U/6.3V_4  [C0402]  187.99 63.21 180 bottom
C1028  10U/6.3V_4  [C0402]  187.99 64.23 180 bottom
C1029  0.1U/16V_2  [C0201]  137.47 26.38 270 bottom
C1031  *0.1u/16V_4  [C0402]  142.02 23.84 0 bottom
C1032  1U/6.3V_2  [C0201]  117.51 27.27 270 bottom
C1033  1U/6.3V_2  [C0201]  127.92 27.27 270 bottom
C1034  1U/6.3V_2  [C0201]  142.02 27.27 270 bottom
C1035  1U/6.3V_2  [C0201]  161.58 27.29 270 bottom
C1036  1U/6.3V_2  [C0201]  169.2 44.41 0 top
C1037  1U/6.3V_2  [C0201]  123.43 27.24 270 bottom
C1038  1U/6.3V_2  [C0201]  125.38 44.41 180 top
C1039  1U/6.3V_2  [C0201]  160.2 27.27 270 bottom
C1040  10U/6.3V_4  [C0402]  113.82 44.41 0 bottom
C1041  10U/6.3V_4  [C0402]  135.41 44.41 0 bottom
C1042  10U/6.3V_4  [C0402]  164.12 44.41 0 bottom
C1043  10U/6.3V_4  [C0402]  152.81 44.41 180 bottom
C1044  10U/6.3V_4  [C0402]  138.34 44.41 180 bottom
C1045  10U/6.3V_4  [C0402]  161.07 44.41 0 bottom
C1046  10U/6.3V_4  [C0402]  174.15 44.41 0 bottom
C1047  10U/6.3V_4  [C0402]  115.6 44.41 180 bottom
C1048  0.1U/16V_2  [C0201]  157.64 44.41 180 bottom
C1049  1U/6.3V_2  [C0201]  181.39 44.03 0 bottom
C1050  *2.2U/10V_4  [C0402]  136.43 26.38 270 bottom
C1051  1U/6.3V_2  [C0201]  181.39 44.79 0 bottom
C1052  10U/6.3V_4  [C0402]  179.99 44.41 0 bottom
C1053  *1U/6.3V_2  [C0201]  184.44 43.78 0 top
C1054  1U/6.3V_2  [C0201]  170.59 21.3 270 bottom
C1055  10U/6.3V_4  [C0402]  184.06 44.67 180 top
C1056  10U/6.3V_4  [C0402]  182.15 43.91 0 top
C1057  0.1U/16V_2  [C0201]  175.42 24.09 90 bottom
C1058  2.2U/10V_4  [C0402]  174.53 24.09 270 bottom
C1059  *0.1u/16V_4  [C0402]  142.02 24.86 0 bottom
C1060  1U/6.3V_2  [C0201]  118.9 44.41 0 top
C1061  1U/6.3V_2  [C0201]  144.69 44.41 0 bottom
C1062  1U/6.3V_2  [C0201]  171.1 26.89 270 bottom
C1063  1U/6.3V_2  [C0201]  125.38 44.41 180 bottom
C1064  1U/6.3V_2  [C0201]  172.24 26.89 270 bottom
C1065  1U/6.3V_2  [C0201]  134.02 44.41 0 bottom
C1066  10U/6.3V_4  [C0402]  188.75 58.38 0 top
C1067  1U/6.3V_2  [C0201]  162.47 44.41 0 bottom
C1068  1U/6.3V_2  [C0201]  169.2 44.41 0 bottom
C1069  1U/6.3V_2  [C0201]  172.37 44.41 0 bottom
C1070  0.1U/16V_2  [C0201]  176.21 24.12 90 bottom
C1071  1U/6.3V_2  [C0201]  131.86 44.41 0 bottom
C1072  2.2U/10V_4  [C0402]  179.89 44.41 180 top
C1073  10U/6.3V_4  [C0402]  120.68 44.41 180 bottom
C1074  10U/6.3V_4  [C0402]  130.21 44.41 0 bottom
C1075  10U/6.3V_4  [C0402]  141 44.41 0 bottom
C1076  10U/6.3V_4  [C0402]  122.71 44.41 180 bottom
C1077  10U/6.3V_4  [C0402]  167.67 44.41 180 bottom
C1078  10U/6.3V_4  [C0402]  165.89 44.41 180 bottom
C1079  10U/6.3V_4  [C0402]  128.43 44.41 180 bottom
C1080  10U/6.3V_4  [C0402]  151.04 44.41 0 bottom
C1081  0.1U/16V_2  [C0201]  153.96 24.86 0 bottom
C1082  10U/6.3V_4  [C0402]  187.99 65.24 180 bottom
C1083  *2.2U/10V_6  [C0603]  154.21 22.82 90 bottom
C1084  10U/6.3V_4  [C0402]  188.12 66.26 180 bottom
C1085  1U/6.3V_2  [C0201]  172.45 21.3 270 bottom
C1086  *1U/6.3V_4  [C0402]  173.39 21.3 90 bottom
C1087  0.1U/16V_2  [C0201]  154.49 26.89 180 bottom
C1088  0.022U/25V_4  [C0402]  149.89 22.82 270 bottom
C1090  1U/6.3V_2  [C0201]  118.9 44.41 0 bottom
C1091  1U/6.3V_2  [C0201]  168.79 26.86 270 bottom
C1092  1U/6.3V_2  [C0201]  170.59 44.41 180 bottom
C1093  *0.1u/16V_4  [C0402]  142.02 25.87 0 bottom
C1094  1U/6.3V_2  [C0201]  167.65 26.86 270 bottom
C1095  1U/6.3V_2  [C0201]  133 44.41 180 bottom
C1096  10U/6.3V_4  [C0402]  188.75 57.37 0 top
C1097  1U/6.3V_2  [C0201]  143.67 44.41 0 bottom
C1098  1U/6.3V_2  [C0201]  154.21 44.41 0 bottom
C1099  1U/6.3V_2  [C0201]  131.86 44.41 180 top
C1100  1U/6.3V_2  [C0201]  126.91 44.41 0 bottom
C1101  0.1U/16V_2  [C0201]  173.39 24.12 90 bottom
C1102  1U/6.3V_2  [C0201]  117.38 44.41 0 bottom
C1103  2.2U/10V_4  [C0402]  188.5 59.78 180 top
C1104  10U/6.3V_4  [C0402]  115.6 44.41 0 top
C1105  10U/6.3V_4  [C0402]  138.34 44.41 180 top
C1106  10U/6.3V_4  [C0402]  122.71 44.41 180 top
C1107  10U/6.3V_4  [C0402]  128.43 44.41 180 top
C1108  10U/6.3V_4  [C0402]  152.81 44.41 180 top
C1109  10U/6.3V_4  [C0402]  164.12 44.41 0 top
C1110  10U/6.3V_4  [C0402]  151.04 44.41 0 top
C1111  10U/6.3V_4  [C0402]  167.67 44.41 180 top
C1112  0.1U/16V_2  [C0201]  153.96 25.87 0 bottom
C1113  10U/6.3V_4  [C0402]  189.47 37.17 270 bottom
C1114  *2.2U/10V_6  [C0603]  152.69 22.82 90 bottom
C1115  10U/6.3V_4  [C0402]  188.37 37.17 270 bottom
C1116  1U/6.3V_2  [C0201]  175.55 21.3 270 bottom
C1117  *1U/6.3V_4  [C0402]  174.4 21.3 90 bottom
C1119  0.1u/16V_4  [C0402]  29.75 87.34 0 bottom
C1120  0.1u/16V_4  [C0402]  29.75 88.36 0 bottom
C1121  0.1u/16V_4  [C0402]  25.86 104.36 270 bottom
C1122  0.1u/16V_4  [C0402]  26.88 104.36 270 bottom
C1123  0.1U/16V_2  [C0201]  140.54 24.22 90 bottom
C1124  0.1U/16V_2  [C0201]  157.26 24.73 180 bottom
C2003  22u/6.3V_6  [C0603]  227.49 150.37 180 top
C2004  22u/6.3V_6  [C0603]  228.45 146.4 180 top
C2005  22u/6.3V_6  [C0603]  193.58 144.49 0 top
C2006  *22u/6.3V_6  [C0603]  208.98 143.9 90 top
C2007  *22u/6.3V_6  [C0603]  202.57 141.34 90 top
C2008  22u/6.3V_6  [C0603]  193.33 132.83 180 top
C2009  10u/6.3V_6  [C0603]  191.8 80.74 0 top
C2027  4.7u/6.3V_6  [C0603]  189.16 79.64 180 top
C2028  4.7u/6.3V_6  [C0603]  191.8 82.26 0 top
C2038  1u/6.3V_4  [C0402]  191.42 79.47 0 top
C2042  10u/6.3V_6  [C0603]  189.16 82.62 180 top
C2043  22u/6.3V_6  [C0603]  189.19 84.06 0 top
C2044  4.7u/6.3V_6  [C0603]  189.16 81.17 0 top
C2045  1u/6.3V_4  [C0402]  202.72 104.83 0 top
C2046  4.7u/6.3V_6  [C0603]  232.39 124.95 180 bottom
C2047  10u/6.3V_6  [C0603]  206.66 90.51 0 top
C2048  22u/6.3V_6  [C0603]  202.85 95.44 0 top
C2049  1u/6.3V_4  [C0402]  207.8 115.15 0 top
C2050  1u/6.3V_4  [C0402]  201.33 105.25 90 top
C2051  0.1u/16V_4  [C0402]  220 119.6 0 top
C2052  0.1u/16V_4  [C0402]  231.93 120.21 270 bottom
C2053  22u/6.3V_6  [C0603]  232.39 122.54 180 bottom
C2054  1u/6.3V_4  [C0402]  207.8 114.14 0 top
C2055  1u/6.3V_4  [C0402]  207.8 116.22 0 top
C2056  0.1u/16V_4  [C0402]  219.88 118.27 180 top
C2057  10u/6.3V_4  [C0402]  210.47 118.66 90 top
C2058  22u/6.3V_6  [C0603]  211.69 116.12 0 top
C2059  10u/6.3V_4  [C0402]  217.58 118.84 0 top
C2060  4.7u/6.3V_6  [C0603]  206.66 88.99 0 top
C2061  4.7u/6.3V_6  [C0603]  206.66 92.17 0 top
C2062  4.7u/6.3V_6  [C0603]  206.66 93.69 0 top
C2063  1u/6.3V_4  [C0402]  215.04 120.65 90 top
C2064  0.1u/16V_4  [C0402]  215.75 118.58 90 top
C2065  1u/6.3V_4  [C0402]  211.74 118.2 270 top
C2066  1u/6.3V_4  [C0402]  214.79 118.58 270 top
C2067  1u/6.3V_4  [C0402]  212.76 118.2 270 top
C2068  1u/6.3V_4  [C0402]  213.77 118.58 270 top
C2069  10u/6.3V_4  [C0402]  220.07 116.46 270 top
C2070  22u/6.3V_6  [C0603]  216.31 83.63 180 top
C2071  0.22u/6.3V_2  [C0201]  196.25 111.31 0 top
C2072  10u/6.3V_4  [C0402_2]  210.68 112.19 270 top
C2073  10u/6.3V_4  [C0402_2]  212.2 107.99 180 top
C2074  10u/6.3V_4  [C0402_2]  210.68 114.17 270 top
C2075  *330u/2.5V_3528H1.9  [C3528]  214.51 111.5 270 top
C2076  10u/6.3V_4  [C0402]  214.74 116.57 0 top
C2077  10u/6.3V_4  [C0402]  208.82 118.66 90 top
C2078  10u/6.3V_6  [C0603]  213.39 84.51 180 bottom
C2079  1u/6.3V_4  [C0402]  217.66 114.26 90 top
C2080  0.22u/6.3V_2  [C0201]  196.25 110.55 0 top
C2081  1u/6.3V_4  [C0402]  220 114.66 180 top
C2082  1u/6.3V_4  [C0402]  216.69 114.26 90 top
C2083  1u/6.3V_4  [C0402]  213.62 115 90 top
C2084  0.1u/16V_4  [C0402]  206.03 108.04 180 top
C2085  10u/6.3V_4  [C0402_2]  209.33 115.99 90 top
C2086  10u/6.3V_4  [C0402_2]  214.74 115 90 top
C2087  10u/6.3V_4  [C0402_2]  210.09 109.72 180 top
C2088  1u/6.3V_4  [C0402]  218.65 116.3 270 top
C2089  0.22u/6.3V_2  [C0201]  196.12 113.22 0 top
C2090  1u/6.3V_4  [C0402]  208.5 113.14 0 top
C2091  1u/6.3V_4  [C0402]  220.12 113.37 180 top
C2092  10u/6.3V_6  [C0603]  210.12 90.41 0 bottom
C2093  0.22u/6.3V_2  [C0201]  196.12 112.45 0 top
C2094  10u/6.3V_6  [C0603]  210.06 88.84 0 bottom
C2095  1u/6.3V_4  [C0402]  208.5 112.15 0 top
C2096  10u/6.3V_4  [C0402]  217.56 112.41 180 top
C2097  1u/6.3V_4  [C0402]  217.68 116.3 270 top
C2098  1u/6.3V_4  [C0402]  220.12 112.1 180 top
C2099  10u/6.3V_6  [C0603]  212.35 87.54 180 top
C2100  1u/6.3V_4  [C0402]  208.06 109.15 0 top
C2101  1u/6.3V_4  [C0402]  208.06 110.17 0 top
C2102  0.22u/6.3V_2  [C0201]  194.98 112.2 0 top
C2103  10u/6.3V_4  [C0402]  217.56 110.99 180 top
C2104  0.22u/6.3V_2  [C0201]  194.98 111.44 0 top
C2105  0.1u/16V_4  [C0402]  220.12 111.09 180 top
C2106  0.1u/16V_4  [C0402]  208.06 111.18 0 top
C2107  1u/6.3V_4  [C0402]  220.12 110.07 180 top
C2108  10u/6.3V_4  [C0402]  212.08 110.03 90 top
C2109  10u/6.3V_6  [C0603]  210.22 82.99 0 top
C2110  10u/6.3V_4  [C0402]  214.08 104.83 180 top
C2111  1u/6.3V_4  [C0402]  218.62 114.26 90 top
C2112  1u/6.3V_4  [C0402]  220.2 108.9 180 top
C2113  1u/6.3V_4  [C0402]  210.09 108.64 180 top
C2114  0.22u/6.3V_2  [C0201]  196.25 109.02 0 top
C2115  0.22u/6.3V_2  [C0201]  196.25 109.79 0 top
C2116  1u/6.3V_4  [C0402]  213.55 108.02 270 top
C2117  1u/6.3V_4  [C0402]  214.58 108.02 270 top
C2118  1u/6.3V_4  [C0402]  215.54 108.02 270 top
C2119  10u/6.3V_4  [C0402]  217.73 108 0 top
C2120  1u/6.3V_4  [C0402]  220.2 107.88 180 top
C2121  *1u/6.3V_4  [C0402]  216.72 116.3 270 top
C2122  22u/6.3V_6  [C0603]  214.49 106.32 180 top
C2123  22u/6.3V_6  [C0603]  217.56 109.41 180 top
C2124  22u/6.3V_6  [C0603]  213.65 84.65 180 top
C2125  0.1u/16V_4  [C0402]  207.17 106.61 180 top
C2126  1u/6.3V_4  [C0402]  210.09 107.63 180 top
C2127  1u/6.3V_4  [C0402]  220.2 106.87 180 top
C2128  10u/6.3V_4  [C0402]  211.74 105.75 90 top
C2129  10u/6.3V_4  [C0402]  217.66 105.75 90 top
C2130  1u/6.3V_4  [C0402]  216.47 106.14 90 top
C2131  10u/6.3V_6  [C0603]  210.22 84.51 0 top
C2132  0.1u/16V_4  [C0402]  220.2 104.76 180 top
C2133  0.1u/16V_4  [C0402]  207.45 105.21 90 top
C2134  1u/6.3V_4  [C0402]  210.09 106.66 180 top
C2135  0.22u/6.3V_2  [C0201]  195.87 107.5 0 top
C2136  0.22u/6.3V_2  [C0201]  195.87 106.74 0 top
C2137  0.22u/6.3V_2  [C0201]  194.6 107.88 0 top
C2138  0.22u/6.3V_2  [C0201]  194.6 108.64 0 top
C2139  10u/6.3V_6  [C0603]  250.73 105.52 0 top
C2140  0.22u/6.3V_2  [C0201]  198.28 105.25 90 top
C2141  0.22u/6.3V_2  [C0201]  199.04 105.25 90 top
C2142  1u/6.3V_4  [C0402]  220.2 105.85 0 top
C2143  0.1u/16V_4  [C0402]  218.85 106.18 90 top
C2144  0.22u/6.3V_2  [C0201]  197.14 105.72 0 top
C2145  0.22u/6.3V_2  [C0201]  197.14 106.48 0 top
C2146  *330u/2.5V_3528H1.9  [C3528]  214.33 81.19 180 top
C2147  0.1u/16V_4  [C0402]  221.52 84.11 0 bottom
C2148  4.7u/6.3V_6  [C0603]  233.59 91.88 270 bottom
C2149  0.1u/16V_4  [C0402]  230.97 89.22 0 top
C2150  22u/6.3V_6  [C0603]  213.52 93.53 180 top
C2151  0.1u/16V_4  [C0402]  206.43 105.21 90 top
C2153  0.1u/16V_4  [C0402]  208.46 105.21 270 top
C2154  10u/6.3V_6  [C0603]  209.71 90.77 0 top
C2155  0.1u/16V_4  [C0402]  205.14 105.21 90 top
C2156  10u/6.3V_6  [C0603]  212.35 86.1 180 top
C2157  10u/6.3V_6  [C0603]  209.71 88.99 0 top
C2158  22u/6.3V_6  [C0603]  213.52 95.05 180 top
C2159  0.1u/16V_4  [C0402]  204.12 105.21 90 top
C2160  10u/6.3V_6  [C0603]  209.71 93.69 0 top
C2161  *0.1u/16V_4  [C0402]  195.87 90.77 180 bottom
C2162  10u/6.3V_6  [C0603]  209.71 92.22 0 top
C2164  22u/6.3V_6  [C0603]  213.52 92.01 180 top
C2166  *220p/50V_4  [C0402]  218.6 88.32 180 top
C2167  *220p/50V_4  [C0402]  218.6 86.29 0 top
C2168  10u/6.3V_6  [C0603]  192.43 145.84 270 bottom
C2169  *22u/6.3V_6  [C0603]  226.09 133.03 0 bottom
C2170  *22u/6.3V_6  [C0603]  193.68 134.36 0 top
C2171  22u/6.3V_6  [C0603]  245.41 130.45 0 bottom
C2172  22u/6.3V_6  [C0603]  248.11 130.45 180 bottom
C2173  *22u/6.3V_6  [C0603]  235.14 125.48 90 bottom
C2174  10u/6.3V_6  [C0603]  213.39 87.56 180 bottom
C2175  10u/6.3V_6  [C0603]  213.39 86.04 180 bottom
C2176  22u/6.3V_6  [C0603]  212.08 112.72 270 top
C2177  *10u/6.3V_6  [C0603]  253.78 105.88 90 bottom
C2178  330u/2.5V_3528H1.9  [C3528]  207.17 81.85 270 top
C2179  10u/6.3V_6  [C0603]  213.52 91.88 180 bottom
C2180  10u/6.3V_6  [C0603]  209.71 94.93 0 bottom
C2181  *10u/6.3V_6  [C0603]  248.95 96.32 0 bottom
C2182  10p/50V_4  [C0402]  226.33 93.67 0 bottom
C2183  10p/50V_4  [C0402]  228.23 93.67 180 bottom
C2184  10u/6.3V_6  [C0603]  213.52 94.93 180 bottom
C2185  10u/6.3V_6  [C0603]  209.71 93.4 0 bottom
C2186  22u/6.3V_6  [C0603]  209.71 91.88 0 bottom
C2187  10u/6.3V_6  [C0603]  213.52 93.4 180 bottom
C2188  0.22u/6.3V_2  [C0201]  194.47 114.1 0 top
C2189  0.22u/6.3V_2  [C0201]  194.47 113.34 0 top
C2190  0.22u/6.3V_2  [C0201]  195.74 114.36 0 top
C2191  0.22u/6.3V_2  [C0201]  195.74 115.12 0 top
C2192  0.22u/6.3V_2  [C0201]  195.87 116.64 0 top
C2193  0.22u/6.3V_2  [C0201]  195.87 115.88 0 top
C2194  0.22u/6.3V_2  [C0201]  194.6 117.03 0 top
C2195  0.22u/6.3V_2  [C0201]  194.6 117.79 0 top
C2196  0.22u/6.3V_2  [C0201]  194.34 119.31 0 top
C2197  0.22u/6.3V_2  [C0201]  194.34 118.55 0 top
C2198  0.22u/6.3V_2  [C0201]  196.25 118.93 0 top
C2199  0.22u/6.3V_2  [C0201]  196.25 119.69 0 top
C2200  0.22u/6.3V_2  [C0201]  195.87 121.22 0 top
C2201  0.22u/6.3V_2  [C0201]  195.87 120.45 0 top
C2202  0.22u/6.3V_2  [C0201]  195.87 121.98 0 top
C2203  0.22u/6.3V_2  [C0201]  195.87 122.74 0 top
C2215  *220p/50V_4  [C0402]  234.73 63.21 90 top
C2216  *220p/50V_4  [C0402]  236 61.18 270 top
C2217  *220p/50V_4  [C0402]  233.31 89.27 90 top
C2218  *220p/50V_4  [C0402]  236.63 87.05 270 top
C2219  *220p/50V_4  [C0402]  234.73 71.08 0 top
C2220  *220p/50V_4  [C0402]  234.47 69.69 90 top
C2221  0.1u/16V_4  [C0402]  209.48 105.21 270 top
C2222  4.7u/6.3V_4  [C0402]  206.66 120.57 90 top
C2223  0.1u/16V_4  [C0402]  207.04 117.21 0 top
C2224  0.1u/16V_4  [C0402]  207.04 118.2 0 top
C2225  1u/6.3V_4  [C0402]  204.63 120.49 0 top
C2226  4.7u/6.3V_6  [C0603]  209.46 85.94 180 top
C2227  4.7u/6.3V_6  [C0603]  209.46 87.47 180 top
C2228  0.1u/16V_4  [C0402]  222.41 79.85 180 top
C2229  *0.1u/16V_4  [C0402]  221.52 83.66 0 top
C2230  0.1u/16V_4  [C0402]  261.78 58.89 135 top
C2231  220p/50V_4  [C0402]  220.25 81.62 0 top
C2500  22u/6.3V_6  [C0603]  193.58 147.54 0 top
C2501  10u/6.3V_6  [C0603]  214.4 148.76 270 top
C2502  1u/6.3V_4  [C0402]  228.16 148.72 0 top
C2503  10u/6.3V_6  [C0603]  207.55 149.44 0 top
C2504  22u/6.3V_6  [C0603]  220.63 148.17 90 top
C2505  22u/6.3V_6  [C0603]  200.44 148.81 270 top
C2506  1u/6.3V_4  [C0402]  228.16 147.71 0 top
C2507  10u/6.3V_6  [C0603]  193.58 146.01 0 top
C2508  1u/6.3V_4  [C0402]  214.4 146.46 270 top
C2509  1u/6.3V_4  [C0402]  207.75 146.35 270 top
C2510  22u/6.3V_6  [C0603]  220.63 145.51 90 top
C2511  1u/6.3V_4  [C0402]  214.4 144.69 270 top
C2512  1u/6.3V_4  [C0402]  207.75 144.57 270 top
C2513  820p/50V_4  [C0402]  228.15 143.91 180 top
C2514  22u/6.3V_6  [C0603]  202.6 137.25 90 top
C2515  820p/50V_4  [C0402]  193.27 143.17 0 top
C2516  1u/6.3V_4  [C0402]  216.69 142.54 0 top
C2517  1u/6.3V_4  [C0402]  208.13 141.65 90 top
C2518  1u/6.3V_4  [C0402]  193.27 141.03 180 top
C2519  1u/6.3V_4  [C0402]  228.15 139.85 0 top
C2520  1u/6.3V_4  [C0402]  193.27 140.01 180 top
C2521  1u/6.3V_4  [C0402]  214.53 139.36 90 top
C2522  1u/6.3V_4  [C0402]  208 138.98 90 top
C2523  1u/6.3V_4  [C0402]  228.15 138.83 0 top
C2524  22u/6.3V_6  [C0603]  193.64 138.77 0 top
C2525  10u/6.3V_6  [C0603]  214.53 137.07 90 top
C2526  22u/6.3V_6  [C0603]  193.62 137.31 0 top
C2527  0.01U/50V_4  [C0402]  201.23 143.19 180 top
C2528  10u/6.3V_6  [C0603]  193.62 135.78 0 top
C2529  0.01u/50V_4  [C0402]  221.82 143.7 270 top
C2530  1u/6.3V_4  [C0402]  237.27 126.3 270 top
C2531  1u/6.3V_4  [C0402]  242.98 127.31 270 top
C2532  22u/6.3V_6  [C0603]  250.47 129.5 0 top
C2533  1u/6.3V_4  [C0402]  246.05 129.01 180 top
C2534  1u/6.3V_4  [C0402]  247.9 129.01 0 top
C2535  820p/50V_4  [C0402]  244.5 127.34 90 top
C2536  0.01u/50V_4  [C0402]  246.36 122.57 90 top
C2537  22u/6.3V_6  [C0603]  248.32 122.39 0 top
C2538  22u/6.3V_6  [C0603]  252.36 121.38 0 top
C2539  1u/6.3V_4  [C0402]  247.32 119.34 0 top
C2540  1u/6.3V_4  [C0402]  243.55 115.6 0 top
C2541  10u/6.3V_6  [C0603]  239.18 115.58 0 top
C2542  1u/6.3V_4  [C0402]  241.59 115.58 180 top
C2543  1u/6.3V_4  [C0402]  248.44 115.53 180 top
C2544  10u/6.3V_6  [C0603]  250.73 115.53 180 top
C2545  10u/6.3V_6  [C0603]  249.71 111.47 180 top
C2546  10u/6.3V_6  [C0603]  238.27 110.77 0 top
C2547  1u/6.3V_4  [C0402]  247.43 110.71 0 top
C2548  1u/6.3V_4  [C0402]  240.57 110.71 180 top
C2549  1u/6.3V_4  [C0402]  242.35 110.71 180 top
C2550  1u/6.3V_4  [C0402]  246.41 108.17 180 top
C2551  22u/6.3V_6  [C0603]  247.39 104.86 0 top
C2552  22u/6.3V_6  [C0603]  249.3 103.44 180 top
C2553  0.01u/50V_4  [C0402]  245.19 104.35 180 top
C2554  1u/6.3V_4  [C0402]  249.7 97.06 0 top
C2555  22u/6.3V_6  [C0603]  237.14 96.61 0 bottom
C2556  1u/6.3V_4  [C0402]  248.19 97.12 270 top
C2557  1u/6.3V_4  [C0402]  247.17 97.63 270 top
C2558  820p/50V_4  [C0402]  240.32 93.78 90 bottom
C2559  1u/6.3V_4  [C0402]  249.7 96.04 0 top
C2560  10u/6.3V_6  [C0603]  209.75 148.61 270 bottom
C2561  22u/6.3V_6  [C0603]  212.39 148.59 270 bottom
C2562  10u/6.3V_6  [C0603]  212.39 145.93 270 bottom
C2563  10u/6.3V_6  [C0603]  209.75 145.81 270 bottom
C2564  1u/6.3V_4  [C0402]  192.61 143.58 90 bottom
C2565  1u/6.3V_4  [C0402]  192.61 141.75 270 bottom
C2566  22u/6.3V_6  [C0603]  192.46 139.51 90 bottom
C2567  22u/6.3V_6  [C0603]  192.46 136.85 90 bottom
C2568  22u/6.3V_6  [C0603]  240.02 130.45 180 bottom
C2569  22u/6.3V_6  [C0603]  250.75 130.45 180 bottom
C2570  10u/6.3V_6  [C0603]  247.88 114.97 180 bottom
C2571  10u/6.3V_6  [C0603]  250.71 114.97 180 bottom
C2572  10u/6.3V_6  [C0603]  247.07 111.85 0 bottom
C2573  10u/6.3V_6  [C0603]  249.74 111.85 180 bottom
C2574  22u/6.3V_6  [C0603]  239.17 96.07 90 bottom
C2575  22u/6.3V_6  [C0603]  241.21 96.74 180 bottom
C2576  10u/6.3V_6  [C0603]  224.57 149.95 180 top
C2577  10u/6.3V_6  [C0603]  219.23 150.33 0 top
C2578  1u/6.3V_4  [C0402]  239.05 117.31 0 top
C2579  1u/6.3V_4  [C0402]  245.65 117.18 0 top
C2580  1u/6.3V_4  [C0402]  248.95 117.06 0 top
C2581  1u/6.3V_4  [C0402]  251.24 124.17 180 top
C2582  1u/6.3V_4  [C0402]  244.51 108.68 90 top
C2583  1u/6.3V_4  [C0402]  239.17 108.93 180 top
C2584  1u/6.3V_4  [C0402]  241.71 108.93 180 top
C2585  1u/6.3V_4  [C0402]  247.05 103.6 180 top
C2586  1u/6.3V_4  [C0402]  246.16 126.2 90 top
C2587  1u/6.3V_4  [C0402]  240.82 117.31 0 top
C2588  10u/6.3V_6  [C0603]  250.98 122.9 0 top
C2589  10u/6.3V_6  [C0603]  252 119.22 90 top
C2590  1u/6.3V_4  [C0402]  251.87 126.07 90 top
C2591  1u/6.3V_4  [C0402]  249.71 126.58 180 top
C2592  1u/6.3V_4  [C0402]  216.31 139.79 270 top
C2593  1u/6.3V_4  [C0402]  217.2 147.79 270 top
C2594  1u/6.3V_4  [C0402]  251.87 127.85 90 top
C2595  1u/6.3V_4  [C0402]  242.73 117.18 0 top
C2596  1u/6.3V_4  [C0402]  229.78 137.63 90 bottom
C2597  1u/6.3V_4  [C0402]  229.78 144.24 270 bottom
C2598  1u/6.3V_4  [C0402]  228.15 137.76 0 top
C2599  1u/6.3V_4  [C0402]  225.08 144.57 270 top
C2600  10u/6.3V_6  [C0603]  195.49 151.6 0 top
C2601  10u/6.3V_6  [C0603]  201.33 145.51 90 top
C2602  1u/6.3V_4  [C0402]  248.57 101.44 90 top
C2603  1u/6.3V_4  [C0402]  246.92 101.44 90 top
C2604  1u/6.3V_4  [C0402]  252.76 107.66 90 top
C2605  1u/6.3V_4  [C0402]  253.91 103.6 90 bottom
C2606  1u/6.3V_4  [C0402]  201.71 148.17 90 top
C2607  1u/6.3V_4  [C0402]  207.04 147.79 180 top
C2608  1u/6.3V_4  [C0402]  197.52 146.65 0 top
C2609  1u/6.3V_4  [C0402]  193.83 149.82 180 top
C2610  1u/6.3V_4  [C0402]  253.91 101.82 270 bottom
C2611  1u/6.3V_4  [C0402]  197.64 135.22 0 top
C2612  10u/6.3V_6  [C0603]  244 111.72 270 top
C2613  10u/6.3V_6  [C0603]  252 101.56 90 top
C2614  1u/6.3V_4  [C0402]  203.23 145.73 180 top
C2615  1u/6.3V_4  [C0402]  202.72 149.19 90 top
C2616  1u/6.3V_4  [C0402]  192.56 148.05 90 bottom
C2617  1u/6.3V_4  [C0402]  222.28 149.7 0 top
C2618  1u/6.3V_4  [C0402]  222.03 147.79 270 top
C2619  1u/6.3V_4  [C0402]  223.48 146.27 90 top
C2620  1u/6.3V_4  [C0402]  214.54 141.16 270 top
C2621  1u/6.3V_4  [C0402]  193.83 148.81 180 top
C2622  1u/6.3V_4  [C0402]  196.12 145.76 90 top
C2623  1u/6.3V_4  [C0402]  246.67 96.48 0 bottom
C3000  4.7U/25V_6  [C0603]  71.28 51.27 180 top
C3001  0.1u/16V_4  [C0402]  62.21 63.03 270 bottom
C3002  0.1u/16V_4  [C0402]  64.78 60.37 270 bottom
C3003  0.1u/16V_4  [C0402]  63.76 60.37 270 bottom
C3004  0.1u/25V_4  [C0402]  68.79 51.3 180 bottom
C3006  0.1u/25V_4  [C0402]  70.14 52.54 180 top
C3007  4.7U/25V_6  [C0603]  68.92 52.49 180 bottom
C3008  27P/50V_4  [C0402]  68.87 53.56 0 top
C3009  0.1u/16V_4  [C0402]  63.18 63.03 270 bottom
C3010  0.1u/16V_4  [C0402]  59.09 60.54 270 bottom
C3011  0.1u/16V_4  [C0402]  58.07 60.54 270 bottom
C3012  0.1u/16V_4  [C0402]  57.06 60.54 270 bottom
C3013  0.1u/16V_4  [C0402]  56.04 60.54 270 bottom
C3014  0.1u/16V_4  [C0402]  54.95 62.93 270 bottom
C3015  0.1u/16V_4  [C0402]  53.68 62.93 270 bottom
C3016  1u/6.3V_4  [C0402]  55.4 51.91 270 top
C3017  0.01U/50V_4  [C0402]  50.81 55.82 0 top
C3018  0.1u/16V_4  [C0402]  54.13 57.37 270 top
C3019  10U/6.3V_4  [C0402]  52.1 57.37 270 top
C3020  56p/50V_4  [C0402]  53.12 57.37 270 top
C3021  33p/50V_4  [C0402]  55.15 57.37 270 top
C3022  10P/50V_4  [C0402]  340.04 19.43 90 top
C3023  0.1u/16V_4  [C0402]  49.1 52.57 270 top
C3024  4.7u/6.3V_4  [C0402_2]  46.51 52.57 90 top
C3025  10P/50V_4  [C0402]  47.78 61.05 270 bottom
C3026  10U/6.3V_4  [C0402]  45.22 58.99 0 top
C3027  10P/50V_4  [C0402]  336.33 18.2 270 top
C3028  10P/50V_4  [C0402]  44.69 59.78 270 bottom
C3029  0.1u/16V_4  [C0402]  43.72 52.41 90 top
C3030  4.7u/6.3V_4  [C0402_2]  40.67 49.75 0 top
C3031  *1U/6.3V_4  [C0402]  40.67 50.89 180 top
C3032  10U/6.3V_4  [C0402]  27.36 55.16 0 bottom
C3033  0.1u/16V_4  [C0402]  27.36 56.3 0 bottom
C3034  10U/6.3V_4  [C0402]  28.15 46.98 90 bottom
C3036  22p/50V_4  [C0402]  54.01 51.53 180 bottom
C3037  10U/6.3V_4  [C0402]  47.66 50.76 270 top
C3039  12p/50V_4  [C0402]  29.57 56.43 270 bottom
C3040  12p/50V_4  [C0402]  30.56 56.43 270 bottom
C3041  *10p/50V_4  [C0402]  31.71 56.45 270 bottom
C3042  10U/6.3V_4  [C0402]  10.83 56.61 0 bottom
C3044  4.7u/6.3V_4  [C0402_2]  66.2 60.54 270 bottom
C3045  0.1u/16V_4  [C0402]  67.34 60.54 270 bottom
C3046  0.1u/16V_4  [C0402]  58.45 60.29 90 top
C3047  0.1u/16V_4  [C0402]  60.74 60.29 90 top
C3056  0.1U/16V_4  [C0402]  67.06 67.78 180 bottom
C3057  0.1U/16V_4  [C0402]  67.06 68.75 180 bottom
C3066  0.1U/16V_4  [C0402]  62.01 69.43 90 bottom
C3067  0.1U/16V_4  [C0402]  63.02 69.43 90 bottom
C3068  0.1U/16V_4  [C0402]  73.79 60.16 180 top
C3069  0.1U/16V_4  [C0402]  73.79 61.18 180 top
C3070  0.1U/16V_4  [C0402]  70.64 61.3 180 top
C3071  0.1U/16V_4  [C0402]  70.64 62.32 180 top
C3072  0.1U/16V_4  [C0402]  72.8 62.57 180 top
C3073  0.1U/16V_4  [C0402]  72.8 63.59 180 top
C3074  0.1U/16V_4  [C0402]  70.64 63.72 180 top
C3075  0.1U/16V_4  [C0402]  70.64 64.73 180 top
C3076  0.1U/16V_4  [C0402]  72.8 64.99 180 top
C3077  0.1U/16V_4  [C0402]  72.8 66 180 top
C3078  0.1U/16V_4  [C0402]  70.64 66.13 180 top
C3079  0.1U/16V_4  [C0402]  70.64 67.15 180 top
C3080  0.1U/16V_4  [C0402]  72.55 67.17 180 top
C3081  0.1U/16V_4  [C0402]  72.55 68.19 180 top
C3082  0.1U/16V_4  [C0402]  70.64 68.54 180 top
C3083  0.1U/16V_4  [C0402]  70.64 69.56 180 top
C3084  2.2U/10V_4  [C0402]  59.16 62.5 270 top
C3085  *0.1u/25V_4  [C0402]  53.78 47.79 90 top
C3201  1u/6.3V_4  [C0402]  350.04 87.85 180 bottom
C3202  0.01U/50V_4  [C0402]  357.28 88.74 90 bottom
C3203  0.1u/16V_4  [C0402]  358.3 91.4 270 bottom
C3204  10U/6.3V_4  [C0402]  357.28 91.4 270 bottom
C3205  *0.01U/50V_4  [C0402]  358.3 88.74 90 bottom
C3207  220p/50V_4  [C0402]  357.54 84.16 90 top
C3600  *1000P/50V_4  [C0402]  343.82 16.51 90 top
C3601  0.1u/6.3V_2  [C0201]  345.22 11.93 180 top
C3602  0.1u/6.3V_2  [C0201]  333.92 12.7 270 top
C3603  2.2U/10V_4  [C0402]  346.49 8.38 90 top
C3604  0.1u/6.3V_2  [C0201]  345.6 8.5 90 top
C3605  1u/10V_4  [C0402]  337.34 16.46 90 top
C3606  1u/10V_4  [C0402]  346.11 6.35 180 top
C3607  1u/10V_4  [C0402]  340.01 3.7 270 top
C3608  1u/10V_4  [C0402]  342.81 16.51 90 top
C3609  0.47U/25V_4  [C0402]  346.62 9.77 0 top
C3610  *22p/50V_4  [C0402]  346.23 14.47 180 top
C3611  2.2U/10V_4  [C0402]  341.54 2.78 180 top
C3612  1u/10V_4  [C0402]  342.96 3.32 270 top
C3613  2.2U/10V_4  [C0402]  334.27 5.88 270 top
C3614  2.2U/10V_4  [C0402]  336.71 4.92 90 top
C3615  2.2U/10V_4  [C0402]  334.63 4.46 0 top
C3616  0.1u/6.3V_2  [C0201]  332.8 6.63 0 top
C3617  2.2U/10V_4  [C0402]  332.7 5.58 0 top
C3618  1u/10V_4  [C0402]  341.03 4.19 270 top
C3619  0.1U/16V_2  [C0201]  332.72 10.94 270 top
C3620  0.1U/16V_2  [C0201]  331.96 10.94 270 top
C3621  0.1u/16V_4  [C0402]  346.31 5.35 0 top
C3626  100p/50V_4  [C0402]  348.9 8.12 180 top
C3631  1u/25V_6  [C0603]  353.73 19.14 270 top
C3632  1u/10V_4  [C0402]  352 19.37 180 top
C3633  1u/10V_4  [C0402]  350.43 19.52 270 top
C3634  2.2U/10V_4  [C0402]  356.14 20.16 180 top
C3635  2.2U/10V_4  [C0402]  356.14 21.3 180 top
C3636  2.2U/10V_4  [C0402]  356.14 22.44 180 top
